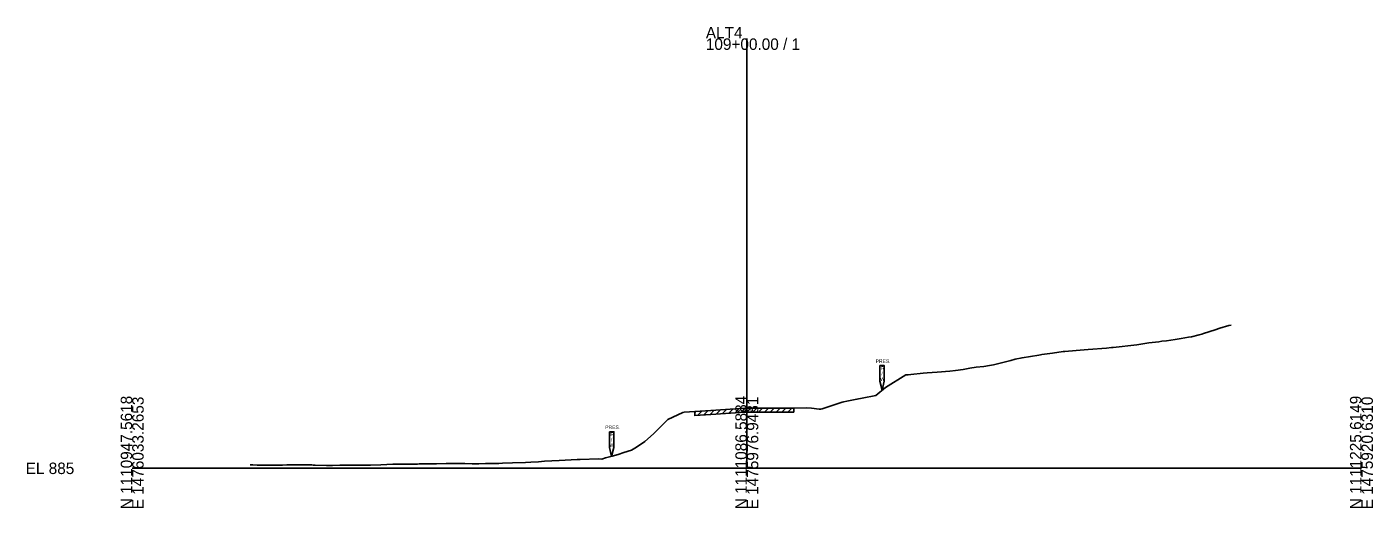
# Model space of a CAD drawing. Extents: x -26 to 1303, y -10 to 19562.
# Drawn here: x 974.3 to 1302.8, y 5490.3 to 5607.6 of the extents above; entities that cross this region are included whole.
import ezdxf

# ---------------------------------------------------------------- set-up
doc = ezdxf.new("R2010")
doc.units = 0
for name, color, linetype in [('RD_GPK_XS_Cell', 7, 'Continuous'), ('RD_XS_ExGround', 7, 'Continuous'), ('RD_XS_ExPaveRet', 7, 'Continuous'), ('RD_XS_ExRW', 7, 'Continuous'), ('RD_XS_TX_Elev_EX', 7, 'Continuous')]:
    doc.layers.add(name, color=color, linetype=linetype)

msp = doc.modelspace()

# ---------------------------------------------------------------- linework, layer by layer
at = {"layer": 'RD_GPK_XS_Cell'}
for p, q in [((1150, 5500), (1150, 5604.84)), ((1000, 5500), (1150, 5500)), ((1150, 5500), (1300, 5500))]:
    msp.add_line(p, q, dxfattribs=at)
at = {"layer": 'RD_XS_ExGround'}
msp.add_lwpolyline([(1028.78, 5500.85), (1029.45, 5500.85), (1030.49, 5500.79), (1031.22, 5500.76), (1032.96, 5500.75), (1034.46, 5500.73), (1035.09, 5500.74), (1036.66, 5500.79), (1037.7, 5500.83), (1039.7, 5500.87), (1040.93, 5500.86), (1043.84, 5500.81), (1044.17, 5500.8), (1044.65, 5500.78), (1047.41, 5500.68), (1048.92, 5500.69), (1050.64, 5500.74), (1051.22, 5500.76), (1052.64, 5500.76), (1053.88, 5500.75), (1054.72, 5500.74), (1057.12, 5500.73), (1058.13, 5500.76), (1060.64, 5500.87), (1063.59, 5501.01), (1065.6, 5501.03), (1066.83, 5501.04), (1068.63, 5501.05), (1069.65, 5501.05), (1070.06, 5501.07), (1071.04, 5501.06), (1073.3, 5501.08), (1074.26, 5501.09), (1076.62, 5501.16), (1079.77, 5501.18), (1081.17, 5501.14), (1083.01, 5501.13), (1084.61, 5501.13), (1086.25, 5501.14), (1087.37, 5501.17), (1089.48, 5501.21), (1090.38, 5501.22), (1092.81, 5501.31), (1095.96, 5501.42), (1097.29, 5501.47), (1099.19, 5501.62), (1100.59, 5501.72), (1102.43, 5501.84), (1104.2, 5501.89), (1105.67, 5501.96), (1108.58, 5502.12), (1108.91, 5502.13), (1109.32, 5502.14), (1113.78, 5502.28), (1114.65, 5502.27), (1115.54, 5502.57), (1117.15, 5502.95), (1118.62, 5503.36), (1120.01, 5503.87), (1121.85, 5504.45), (1122.63, 5504.94), (1124.56, 5506.15), (1125.09, 5506.5), (1127.24, 5508.39), (1130.06, 5511.24), (1130.7, 5511.89), (1134.42, 5513.65), (1134.73, 5513.68), (1137.31, 5513.83), (1141.18, 5514.08), (1149.55, 5514.65), (1150, 5514.65), (1153.47, 5514.65), (1161.46, 5514.7), (1164.58, 5514.77), (1165.77, 5514.69), (1167.65, 5514.46), (1168.06, 5514.44), (1168.38, 5514.53), (1173.31, 5516.15), (1173.64, 5516.25), (1174.42, 5516.41), (1176.88, 5516.86), (1178.16, 5517.14), (1181.45, 5517.76), (1183.86, 5519.74), (1188.8, 5522.76), (1189.39, 5522.82), (1190.01, 5522.89), (1193.06, 5523.23), (1194.05, 5523.29), (1196.47, 5523.45), (1199.54, 5523.71), (1200.96, 5523.86), (1202.77, 5524.12), (1204.46, 5524.42), (1206.01, 5524.66), (1207.87, 5524.87), (1209.25, 5525.1), (1210.17, 5525.24), (1212.79, 5525.85), (1214.45, 5526.28), (1215.53, 5526.59), (1217.17, 5526.96), (1221.29, 5527.63), (1221.69, 5527.69), (1222, 5527.74), (1224.62, 5528.11), (1227.22, 5528.48), (1227.59, 5528.52), (1230.37, 5528.73), (1233.34, 5528.96), (1237.77, 5529.27), (1238.99, 5529.45), (1239.38, 5529.5), (1245.15, 5530.13), (1248.09, 5530.59), (1250.59, 5530.86), (1251.32, 5530.98), (1252.41, 5531.1), (1254.56, 5531.42), (1256.03, 5531.66), (1257.8, 5531.96), (1258.55, 5532.08), (1260.4, 5532.52), (1261.03, 5532.71), (1261.47, 5532.87), (1264.27, 5533.74), (1265.46, 5534.18), (1267.66, 5534.8), (1268.19, 5534.95)], dxfattribs=at)
at = {"layer": 'RD_XS_ExPaveRet'}
for p, q in [((1137.31, 5513.65), (1137.5, 5513.85)), ((1137.31, 5513.83), (1137.31, 5512.83)), ((1137.94, 5512.88), (1139.01, 5513.94)), ((1139.45, 5512.97), (1140.52, 5514.04)), ((1140.96, 5513.07), (1142.03, 5514.14)), ((1142.48, 5513.17), (1143.55, 5514.24)), ((1144, 5513.27), (1145.07, 5514.34)), ((1145.52, 5513.38), (1146.59, 5514.45)), ((1147.04, 5513.48), (1148.11, 5514.55)), ((1148.55, 5513.59), (1149.62, 5514.65)), ((1150.04, 5513.66), (1151.03, 5514.65)), ((1151.45, 5513.66), (1152.45, 5514.65)), ((1152.87, 5513.66), (1153.86, 5514.65)), ((1154.28, 5513.66), (1155.29, 5514.66)), ((1155.71, 5513.67), (1156.71, 5514.67)), ((1157.13, 5513.68), (1158.13, 5514.68)), ((1158.55, 5513.69), (1159.56, 5514.69)), ((1159.98, 5513.7), (1160.98, 5514.7)), ((1161.4, 5513.71), (1161.46, 5513.76)), ((1161.46, 5514.7), (1161.46, 5513.7))]:
    msp.add_line(p, q, dxfattribs=at)
msp.add_lwpolyline([(1137.31, 5512.84), (1141.25, 5513.09), (1149.59, 5513.66), (1153.47, 5513.66), (1161.46, 5513.71)], dxfattribs=at)
at = {"layer": 'RD_XS_ExRW'}
for points in [[(1182.45, 5525.05), (1183.55, 5525.05), (1183.55, 5521.22), (1183, 5519.04), (1182.45, 5521.22)], [(1116.45, 5508.93), (1117.55, 5508.93), (1117.55, 5505.1), (1117, 5502.92), (1116.45, 5505.1)]]:
    msp.add_lwpolyline(points, close=True, dxfattribs=at)

# ---------------------------------------------------------------- texts
at = {"layer": 'RD_GPK_XS_Cell'}
for s, p in [('ALT4', (1140, 5604.84)), ('109+00.00 / 1', (1140, 5602.04)), ('EL 885', (974, 5498.6))]:
    msp.add_text(s, height=2.8, dxfattribs=at).set_placement(p)
for s, p in [('N 1110947.5618', (1000, 5490)), ('E 1476033.2653', (1002.8, 5490)), ('N 1111086.5884', (1150, 5490)), ('E 1475976.9481', (1152.8, 5490)), ('N 1111225.6149', (1300, 5490)), ('E 1475920.6310', (1302.8, 5490))]:
    msp.add_text(s, height=2.8, rotation=90, dxfattribs=at).set_placement(p)
at = {"layer": 'RD_XS_ExRW'}
for s, p in [('PRES.', (1181.45, 5525.68)), ('R', (1182.71, 5523.96)), ('/', (1182.83, 5522.65)), ('W', (1182.53, 5521.33)), ('PRES.', (1115.45, 5509.56)), ('R', (1116.71, 5507.84)), ('/', (1116.83, 5506.53)), ('W', (1116.53, 5505.21))]:
    msp.add_text(s, height=0.875, dxfattribs=at).set_placement(p)
at = {"layer": 'RD_XS_TX_Elev_EX'}
msp.add_text('899.65', height=0.5, dxfattribs=at).set_placement((1148.98, 5514.15))

doc.saveas('drawing.dxf')
